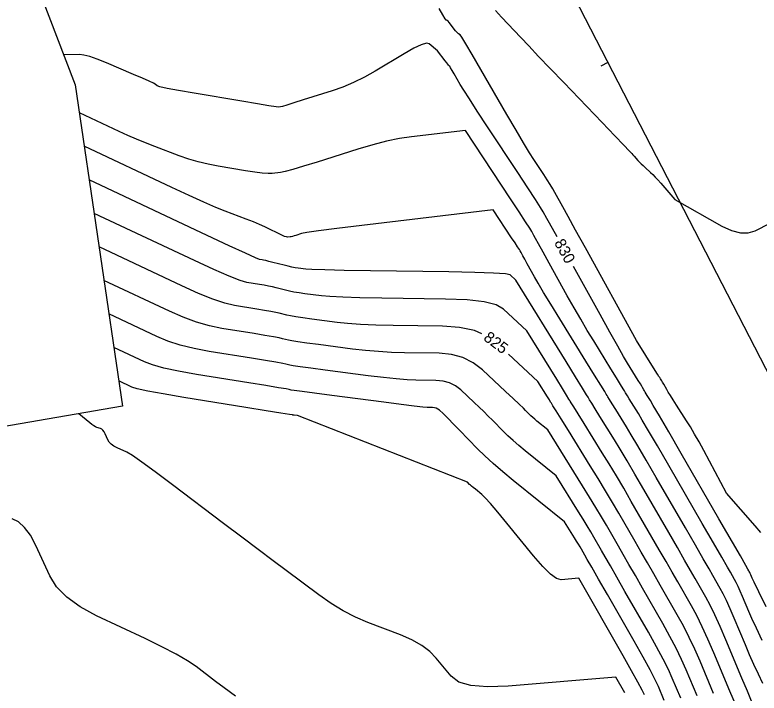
# Model space of a CAD drawing. Extents: x 1715724 to 1716561, y 394063 to 395906.
# Drawn here: x 1716135.4 to 1716227.9, y 394685.4 to 394769.7 of the extents above; entities that cross this region are included whole.
import ezdxf

# ---------------------------------------------------------------- set-up
doc = ezdxf.new("R2010")
doc.units = 0
for name, color, linetype in [('DT_X_Contour_Major', 7, 'Continuous'), ('DT_X_Contour_Minor', 7, 'Continuous'), ('DT_X_TIN_Hull', 7, 'Continuous'), ('GE_P_CL_10', 7, 'Continuous')]:
    doc.layers.add(name, color=color, linetype=linetype)

msp = doc.modelspace()

# ---------------------------------------------------------------- linework, layer by layer
at = {"layer": 'DT_X_Contour_Major'}
for points in [[(1716202.779, 394742.136), (1716201.823, 394743.864), (1716201.508, 394744.435), (1716201.057, 394745.25), (1716200.733, 394745.784), (1716200.099, 394746.776), (1716199.154, 394748.226), (1716197.898, 394750.134), (1716194.137, 394755.831), (1716192.867, 394757.762), (1716191.879, 394759.282), (1716191.172, 394760.391), (1716190.747, 394761.09), (1716189.989, 394762.404), (1716189.738, 394762.837), (1716189.553, 394763.149), (1716189.435, 394763.341), (1716189.384, 394763.412), (1716189.336, 394763.443), (1716189.294, 394763.487), (1716189.205, 394763.594), (1716189.068, 394763.766), (1716188.884, 394764.002), (1716187.916, 394765.253), (1716186.9, 394766.133), (1716186.541, 394766.197), (1716185.9, 394766.012), (1716184.978, 394765.579), (1716183.774, 394764.898), (1716180.187, 394762.749), (1716178.843, 394761.991), (1716177.5, 394761.329), (1716176.158, 394760.762), (1716174.817, 394760.291), (1716171.245, 394759.163), (1716170.063, 394758.791), (1716169.197, 394758.523), (1716168.647, 394758.359), (1716168.413, 394758.298), (1716168.21, 394758.274), (1716167.866, 394758.313), (1716166.986, 394758.446), (1716165.569, 394758.675), (1716163.616, 394758.999), (1716157.693, 394759.99), (1716155.739, 394760.325), (1716154.318, 394760.588), (1716153.432, 394760.779), (1716153.081, 394760.898), (1716152.854, 394761.118), (1716152.623, 394761.256), (1716152.098, 394761.506), (1716151.279, 394761.868), (1716150.168, 394762.342), (1716146.812, 394763.755), (1716145.659, 394764.217), (1716144.715, 394764.545), (1716143.981, 394764.738), (1716143.457, 394764.796), (1716141.5, 394764.752)], [(1716193.44, 394730.1), (1716192.514, 394730.491), (1716190.668, 394730.894), (1716188.522, 394731.05), (1716182.397, 394731.137), (1716180.24, 394731.184), (1716178.361, 394731.262), (1716176.761, 394731.371), (1716175.44, 394731.509), (1716172.289, 394731.92), (1716171.21, 394732.066), (1716170.339, 394732.196), (1716169.674, 394732.311), (1716169.217, 394732.409), (1716168.272, 394732.652), (1716167.832, 394732.753), (1716167.219, 394732.873), (1716166.433, 394733.013), (1716165.474, 394733.173), (1716162.688, 394733.625), (1716161.497, 394733.904), (1716160.016, 394734.4), (1716158.244, 394735.114), (1716156.18, 394736.046), (1716145.873, 394740.903)], [(1716228.745, 394696.184), (1716227.834, 394698.044), (1716227.259, 394699.225), (1716227.022, 394699.728), (1716226.84, 394700.165), (1716226.774, 394700.319), (1716226.714, 394700.451), (1716226.66, 394700.562), (1716226.612, 394700.651), (1716226.492, 394700.862), (1716226.233, 394701.311), (1716225.545, 394702.502), (1716222.885, 394707.108), (1716218.197, 394715.226), (1716216.64, 394717.92), (1716215.485, 394719.912), (1716214.733, 394721.204), (1716214.383, 394721.794), (1716213.986, 394722.434), (1716213.848, 394722.657), (1716213.731, 394722.847), (1716213.637, 394723.004), (1716213.564, 394723.127), (1716213.399, 394723.412), (1716213.298, 394723.581), (1716213.12, 394723.874), (1716212.864, 394724.291), (1716212.53, 394724.831), (1716211.538, 394726.438), (1716211.044, 394727.269), (1716210.308, 394728.556), (1716209.33, 394730.299), (1716208.109, 394732.498), (1716204.812, 394738.46)], [(1716222.214, 394685.387), (1716220.534, 394689.404), (1716219.884, 394690.895), (1716219.193, 394692.356), (1716218.462, 394693.786), (1716217.69, 394695.186), (1716215.579, 394698.88), (1716214.792, 394700.256), (1716214.012, 394701.615), (1716213.24, 394702.957), (1716212.477, 394704.281), (1716210.451, 394707.789), (1716209.659, 394709.145), (1716208.802, 394710.582), (1716207.88, 394712.101), (1716206.894, 394713.701), (1716204.177, 394718.077), (1716203.285, 394719.514), (1716202.646, 394720.543), (1716202.261, 394721.164), (1716202.129, 394721.377), (1716202.115, 394721.402), (1716202.078, 394721.461), (1716201.979, 394721.622), (1716201.818, 394721.883), (1716201.594, 394722.246), (1716200.404, 394724.173), (1716196.759, 394727.579)], [(1716211.199, 394685.469), (1716210.073, 394687.438), (1716196.713, 394686.317), (1716194.122, 394686.213), (1716192.073, 394686.382), (1716190.566, 394686.823), (1716189.602, 394687.537), (1716187.756, 394689.804), (1716186.959, 394690.621), (1716185.955, 394691.371), (1716184.743, 394692.055), (1716183.323, 394692.671), (1716179.261, 394694.226), (1716177.738, 394694.878), (1716176.216, 394695.667), (1716174.696, 394696.593), (1716173.177, 394697.656), (1716169.127, 394700.674), (1716167.501, 394701.889), (1716165.66, 394703.272), (1716163.604, 394704.823), (1716161.333, 394706.541), (1716154.989, 394711.347), (1716152.852, 394712.95), (1716151.197, 394714.155), (1716150.024, 394714.962), (1716149.334, 394715.371), (1716148.138, 394715.932), (1716147.729, 394716.151), (1716147.4, 394716.388), (1716147.151, 394716.643), (1716146.982, 394716.915), (1716146.638, 394717.665), (1716146.505, 394717.917), (1716146.363, 394718.111), (1716146.213, 394718.247), (1716146.054, 394718.324), (1716145.62, 394718.453), (1716145.442, 394718.526), (1716145.232, 394718.647), (1716144.991, 394718.817), (1716144.718, 394719.036), (1716143.373, 394720.171)]]:
    msp.add_lwpolyline(points, dxfattribs=at)
at = {"layer": 'DT_X_Contour_Minor'}
for points in [[(1716228.095, 394705.417), (1716227.375, 394706.241), (1716223.833, 394710.289), (1716221, 394715.579), (1716220.411, 394716.661), (1716219.858, 394717.641), (1716219.341, 394718.518), (1716218.86, 394719.293), (1716217.625, 394721.223), (1716217.202, 394721.887), (1716216.858, 394722.434), (1716216.593, 394722.863), (1716216.408, 394723.174), (1716216.021, 394723.846), (1716215.888, 394724.075), (1716215.781, 394724.257), (1716215.699, 394724.393), (1716215.643, 394724.482), (1716215.527, 394724.657), (1716215.437, 394724.798), (1716215.254, 394725.092), (1716214.977, 394725.538), (1716212.662, 394729.282), (1716206.301, 394740.785), (1716205.079, 394742.994), (1716204.14, 394744.692), (1716203.484, 394745.879), (1716202.492, 394747.672), (1716202.232, 394748.125), (1716201.916, 394748.647), (1716201.544, 394749.237), (1716201.115, 394749.895), (1716199.897, 394751.739), (1716199.345, 394752.608), (1716198.604, 394753.83), (1716197.674, 394755.406), (1716196.553, 394757.336), (1716193.313, 394762.953), (1716192.24, 394764.802), (1716191.452, 394766.137), (1716190.948, 394766.957), (1716190.728, 394767.263), (1716190.522, 394767.394), (1716190.431, 394767.466), (1716190.315, 394767.584), (1716190.172, 394767.749), (1716190.004, 394767.96), (1716189.521, 394768.584), (1716189.358, 394768.789), (1716189.23, 394768.936), (1716189.138, 394769.025), (1716189.082, 394769.056), (1716188.979, 394769.06), (1716188.858, 394769.225), (1716188.572, 394769.717), (1716188.121, 394770.536)], [(1716195.108, 394770.292), (1716195.887, 394769.459), (1716198.259, 394766.932), (1716199.261, 394765.87), (1716200.487, 394764.579), (1716201.938, 394763.059), (1716203.614, 394761.309), (1716208.382, 394756.34), (1716209.947, 394754.709), (1716211.066, 394753.542), (1716211.739, 394752.841), (1716211.967, 394752.604), (1716211.979, 394752.593), (1716212.006, 394752.564), (1716212.076, 394752.486), (1716212.191, 394752.359), (1716212.349, 394752.184), (1716212.828, 394751.65), (1716213.018, 394751.445), (1716213.227, 394751.231), (1716213.456, 394751.009), (1716213.704, 394750.777), (1716214.394, 394750.149), (1716214.667, 394749.888), (1716214.969, 394749.578), (1716215.3, 394749.219), (1716215.661, 394748.811), (1716217.411, 394746.789), (1716223.261, 394743.49), (1716224.459, 394742.923), (1716225.547, 394742.636), (1716226.524, 394742.629), (1716227.391, 394742.901), (1716231.178, 394744.824)], [(1716228.266, 394691.99), (1716227.535, 394693.515), (1716226.978, 394694.713), (1716226.595, 394695.583), (1716225.807, 394697.466), (1716225.525, 394698.126), (1716225.267, 394698.695), (1716225.035, 394699.172), (1716224.828, 394699.558), (1716224.309, 394700.465), (1716223.944, 394701.1), (1716223.238, 394702.325), (1716222.192, 394704.139), (1716220.804, 394706.543), (1716216.648, 394713.738), (1716215.244, 394716.165), (1716214.149, 394718.046), (1716213.363, 394719.383), (1716212.885, 394720.175), (1716212.024, 394721.562), (1716211.735, 394722.028), (1716211.514, 394722.386), (1716211.362, 394722.636), (1716211.277, 394722.777), (1716211.142, 394723.01), (1716210.998, 394723.248), (1716210.668, 394723.786), (1716210.151, 394724.625), (1716209.447, 394725.764), (1716207.323, 394729.204), (1716206.521, 394730.523), (1716205.707, 394731.9), (1716204.882, 394733.335), (1716204.046, 394734.828), (1716201.801, 394738.888), (1716201.051, 394740.244), (1716200.485, 394741.268), (1716200.103, 394741.959), (1716199.905, 394742.317), (1716199.622, 394742.828), (1716199.379, 394743.223), (1716198.861, 394744.027), (1716198.068, 394745.24), (1716197.001, 394746.86), (1716191.379, 394755.376), (1716184.69, 394754.576), (1716183.2, 394754.351), (1716181.594, 394754.019), (1716179.872, 394753.581), (1716178.036, 394753.036), (1716172.985, 394751.441), (1716171.279, 394750.912), (1716169.949, 394750.521), (1716168.995, 394750.267), (1716168.417, 394750.152), (1716167.375, 394750.028), (1716166.875, 394750.014), (1716166.156, 394750.065), (1716165.216, 394750.18), (1716164.058, 394750.36), (1716160.675, 394750.926), (1716159.422, 394751.165), (1716158.2, 394751.46), (1716157.009, 394751.811), (1716155.848, 394752.216), (1716152.794, 394753.371), (1716151.659, 394753.812), (1716150.546, 394754.27), (1716149.453, 394754.745), (1716148.382, 394755.236), (1716143.433, 394757.569)], [(1716228.351, 394686.627), (1716227.788, 394687.795), (1716227.236, 394688.986), (1716226.696, 394690.2), (1716226.168, 394691.437), (1716224.775, 394694.766), (1716224.275, 394695.933), (1716223.82, 394696.939), (1716223.41, 394697.783), (1716223.043, 394698.465), (1716222.127, 394700.069), (1716221.656, 394700.889), (1716220.932, 394702.148), (1716219.954, 394703.843), (1716218.722, 394705.977), (1716215.099, 394712.251), (1716213.848, 394714.41), (1716212.812, 394716.18), (1716211.992, 394717.562), (1716211.387, 394718.557), (1716210.062, 394720.691), (1716209.623, 394721.4), (1716209.297, 394721.925), (1716209.086, 394722.268), (1716208.99, 394722.427), (1716208.885, 394722.608), (1716208.698, 394722.915), (1716208.216, 394723.698), (1716207.438, 394724.959), (1716206.364, 394726.697), (1716203.108, 394731.969), (1716201.997, 394733.776), (1716201.105, 394735.243), (1716200.434, 394736.371), (1716199.982, 394737.159), (1716199.071, 394738.807), (1716198.767, 394739.357), (1716198.537, 394739.772), (1716198.382, 394740.053), (1716198.302, 394740.198), (1716198.187, 394740.405), (1716198.088, 394740.566), (1716197.878, 394740.892), (1716197.556, 394741.384), (1716197.123, 394742.042), (1716194.841, 394745.498), (1716178.523, 394743.546), (1716175.432, 394743.17), (1716173.151, 394742.879), (1716171.68, 394742.672), (1716171.02, 394742.549), (1716170.34, 394742.334), (1716170.103, 394742.262), (1716169.901, 394742.207), (1716169.735, 394742.168), (1716169.605, 394742.146), (1716169.304, 394742.111), (1716169.15, 394742.128), (1716168.911, 394742.206), (1716168.588, 394742.345), (1716168.181, 394742.545), (1716166.983, 394743.16), (1716166.468, 394743.408), (1716165.821, 394743.691), (1716165.043, 394744.008), (1716164.132, 394744.36), (1716161.53, 394745.344), (1716160.385, 394745.804), (1716158.901, 394746.446), (1716157.079, 394747.271), (1716154.918, 394748.278), (1716144.043, 394753.402)], [(1716226.937, 394684.457), (1716226.414, 394685.688), (1716225.741, 394687.291), (1716223.743, 394692.066), (1716223.026, 394693.741), (1716222.373, 394695.183), (1716221.784, 394696.394), (1716221.259, 394697.372), (1716219.944, 394699.673), (1716219.368, 394700.678), (1716218.625, 394701.97), (1716217.716, 394703.548), (1716216.64, 394705.412), (1716213.549, 394710.763), (1716212.451, 394712.655), (1716211.475, 394714.314), (1716210.622, 394715.742), (1716209.89, 394716.938), (1716208.101, 394719.82), (1716207.51, 394720.771), (1716207.08, 394721.464), (1716206.811, 394721.9), (1716206.703, 394722.077), (1716206.628, 394722.206), (1716206.436, 394722.519), (1716205.917, 394723.362), (1716205.069, 394724.736), (1716203.894, 394726.639), (1716197.644, 394736.757), (1716196.946, 394737.409), (1716196.358, 394737.538), (1716194.893, 394737.645), (1716192.551, 394737.729), (1716189.333, 394737.792), (1716179.58, 394737.93), (1716176.337, 394737.98), (1716173.919, 394738.03), (1716172.329, 394738.078), (1716171.565, 394738.124), (1716170.629, 394738.246), (1716170.256, 394738.303), (1716169.838, 394738.383), (1716169.375, 394738.485), (1716168.867, 394738.61), (1716167.453, 394738.972), (1716166.974, 394739.094), (1716166.596, 394739.187), (1716166.321, 394739.25), (1716166.147, 394739.285), (1716165.82, 394739.338), (1716165.32, 394739.54), (1716164.066, 394740.107), (1716162.059, 394741.039), (1716159.298, 394742.335), (1716144.653, 394749.236)], [(1716224.932, 394684.078), (1716224.256, 394685.674), (1716222.258, 394690.45), (1716221.522, 394692.157), (1716220.813, 394693.698), (1716220.13, 394695.072), (1716219.475, 394696.279), (1716217.762, 394699.276), (1716217.08, 394700.467), (1716216.319, 394701.793), (1716215.478, 394703.252), (1716214.558, 394704.846), (1716212, 394709.276), (1716211.055, 394710.9), (1716210.139, 394712.448), (1716209.251, 394713.921), (1716208.392, 394715.32), (1716206.139, 394718.948), (1716205.398, 394720.142), (1716204.863, 394721.004), (1716204.536, 394721.532), (1716204.416, 394721.727), (1716204.371, 394721.804), (1716204.257, 394721.99), (1716203.948, 394722.492), (1716203.443, 394723.309), (1716202.744, 394724.442), (1716199.024, 394730.465), (1716196.124, 394733.175), (1716195.208, 394733.689), (1716193.703, 394734.068), (1716191.61, 394734.312), (1716188.927, 394734.421), (1716180.989, 394734.533), (1716178.288, 394734.582), (1716176.14, 394734.646), (1716174.545, 394734.724), (1716173.502, 394734.817), (1716171.459, 394735.083), (1716170.733, 394735.184), (1716170.088, 394735.289), (1716169.525, 394735.398), (1716169.042, 394735.51), (1716167.863, 394735.812), (1716167.403, 394735.923), (1716166.907, 394736.03), (1716166.377, 394736.132), (1716165.811, 394736.229), (1716164.254, 394736.481), (1716163.409, 394736.722), (1716162.041, 394737.253), (1716160.151, 394738.076), (1716157.739, 394739.19), (1716145.263, 394745.069)], [(1716220.173, 394685.1), (1716218.81, 394688.358), (1716218.245, 394689.632), (1716217.573, 394691.013), (1716216.793, 394692.5), (1716215.906, 394694.093), (1716213.397, 394698.484), (1716212.503, 394700.045), (1716211.705, 394701.438), (1716211.003, 394702.661), (1716210.395, 394703.716), (1716208.902, 394706.301), (1716208.296, 394707.336), (1716207.599, 394708.501), (1716206.81, 394709.797), (1716205.93, 394711.223), (1716201.609, 394718.181), (1716200.272, 394719.258), (1716200, 394719.482), (1716199.754, 394719.695), (1716199.536, 394719.895), (1716199.346, 394720.083), (1716198.874, 394720.567), (1716198.585, 394720.852), (1716198.071, 394721.343), (1716197.333, 394722.039), (1716196.369, 394722.942), (1716193.501, 394725.623), (1716192.358, 394726.505), (1716191.079, 394727.142), (1716189.666, 394727.534), (1716188.117, 394727.679), (1716183.805, 394727.74), (1716182.191, 394727.786), (1716180.582, 394727.878), (1716178.977, 394728.017), (1716177.377, 394728.202), (1716173.118, 394728.757), (1716171.687, 394728.947), (1716170.589, 394729.103), (1716169.824, 394729.224), (1716169.392, 394729.309), (1716168.682, 394729.491), (1716168.261, 394729.582), (1716167.53, 394729.716), (1716166.489, 394729.895), (1716165.138, 394730.117), (1716161.122, 394730.769), (1716159.586, 394731.085), (1716157.991, 394731.546), (1716156.336, 394732.152), (1716154.622, 394732.901), (1716146.483, 394736.736)], [(1716218.131, 394684.814), (1716217.086, 394687.312), (1716216.607, 394688.37), (1716215.953, 394689.671), (1716215.125, 394691.214), (1716214.122, 394693), (1716211.214, 394698.087), (1716210.215, 394699.834), (1716209.399, 394701.261), (1716208.765, 394702.366), (1716208.313, 394703.15), (1716207.353, 394704.814), (1716206.963, 394705.479), (1716206.514, 394706.229), (1716206.007, 394707.062), (1716205.441, 394707.98), (1716202.661, 394712.457), (1716198.798, 394715.567), (1716198.01, 394716.215), (1716197.302, 394716.829), (1716196.672, 394717.407), (1716196.122, 394717.949), (1716194.76, 394719.349), (1716194.235, 394719.881), (1716193.682, 394720.428), (1716193.101, 394720.988), (1716192.492, 394721.564), (1716190.831, 394723.117), (1716190.168, 394723.628), (1716189.428, 394723.997), (1716188.609, 394724.224), (1716187.711, 394724.308), (1716185.213, 394724.344), (1716184.142, 394724.388), (1716182.802, 394724.495), (1716181.193, 394724.663), (1716179.315, 394724.894), (1716173.948, 394725.593), (1716172.165, 394725.829), (1716170.84, 394726.01), (1716169.974, 394726.136), (1716169.566, 394726.209), (1716169.092, 394726.331), (1716168.69, 394726.411), (1716167.841, 394726.559), (1716166.545, 394726.776), (1716164.801, 394727.061), (1716159.556, 394727.913), (1716157.674, 394728.267), (1716155.965, 394728.693), (1716154.428, 394729.189), (1716153.063, 394729.757), (1716147.094, 394732.57)], [(1716216.089, 394684.527), (1716215.362, 394686.266), (1716214.968, 394687.107), (1716214.333, 394688.328), (1716213.456, 394689.928), (1716212.337, 394691.907), (1716209.032, 394697.691), (1716207.927, 394699.623), (1716207.092, 394701.083), (1716206.527, 394702.07), (1716206.232, 394702.585), (1716205.803, 394703.326), (1716205.63, 394703.623), (1716205.43, 394703.957), (1716205.204, 394704.328), (1716204.951, 394704.737), (1716203.712, 394706.733), (1716197.324, 394711.876), (1716196.021, 394712.948), (1716194.849, 394713.963), (1716193.808, 394714.918), (1716192.898, 394715.816), (1716190.645, 394718.131), (1716189.885, 394718.91), (1716189.293, 394719.513), (1716188.87, 394719.938), (1716188.615, 394720.186), (1716188.16, 394720.611), (1716187.979, 394720.751), (1716187.776, 394720.852), (1716187.551, 394720.914), (1716187.306, 394720.938), (1716186.622, 394720.947), (1716186.094, 394720.99), (1716185.023, 394721.111), (1716183.409, 394721.31), (1716181.253, 394721.587), (1716174.778, 394722.43), (1716172.642, 394722.71), (1716171.091, 394722.916), (1716170.124, 394723.049), (1716169.741, 394723.109), (1716169.501, 394723.171), (1716169.119, 394723.24), (1716168.152, 394723.403), (1716166.601, 394723.658), (1716164.465, 394724.005), (1716157.99, 394725.056), (1716155.763, 394725.449), (1716153.94, 394725.839), (1716152.521, 394726.227), (1716151.504, 394726.612), (1716147.704, 394728.403)], [(1716213.638, 394685.22), (1716213.356, 394685.799), (1716212.817, 394686.803), (1716212.022, 394688.232), (1716210.97, 394690.085), (1716205.461, 394699.723), (1716203.273, 394699.54), (1716202.707, 394699.696), (1716201.948, 394700.244), (1716200.995, 394701.183), (1716199.849, 394702.513), (1716196.534, 394706.583), (1716195.409, 394707.949), (1716194.519, 394708.994), (1716193.863, 394709.719), (1716193.443, 394710.123), (1716192.636, 394710.772), (1716192.364, 394710.993), (1716192.153, 394711.168), (1716192.003, 394711.296), (1716191.915, 394711.379), (1716191.645, 394711.656), (1716170.544, 394719.927), (1716170.107, 394719.984), (1716170.025, 394719.994), (1716169.966, 394720.002), (1716169.93, 394720.007), (1716169.916, 394720.009), (1716169.911, 394720.01), (1716169.548, 394720.07), (1716168.463, 394720.246), (1716166.656, 394720.539), (1716164.128, 394720.949), (1716156.424, 394722.2), (1716153.852, 394722.631), (1716151.915, 394722.986), (1716150.613, 394723.265), (1716149.946, 394723.468), (1716148.314, 394724.236)], [(1716162.817, 394685.053), (1716161.424, 394686.098), (1716160.355, 394686.904), (1716157.937, 394688.736), (1716156.861, 394689.47), (1716155.447, 394690.296), (1716153.693, 394691.216), (1716151.601, 394692.229), (1716145.571, 394695.053), (1716143.512, 394696.157), (1716141.855, 394697.351), (1716140.6, 394698.634), (1716139.749, 394700.006), (1716138.015, 394703.786), (1716137.344, 394705.056), (1716136.63, 394706.034), (1716135.874, 394706.717), (1716135.075, 394707.107)]]:
    msp.add_lwpolyline(points, dxfattribs=at)
at = {"layer": 'DT_X_TIN_Hull'}
msp.add_lwpolyline([(1716124.186, 394809.786), (1716142.923, 394761.049), (1716148.773, 394721.102), (1716073.406, 394708.116)], dxfattribs=at)
at = {"layer": 'GE_P_CL_10'}
for p, q in [((1716249.46, 394685.42), (1715852.538, 395456.564)), ((1716209.1, 394763.833), (1716208.211, 394763.375))]:
    msp.add_line(p, q, dxfattribs=at)

# ---------------------------------------------------------------- texts
at = {"layer": 'DT_X_Contour_Major'}
for s, rotation, p in [('830', 298.94217, (1716202.377, 394741.416)), ('825', 322.78216, (1716193.534, 394729.402))]:
    msp.add_text(s, height=1.4, rotation=rotation, dxfattribs=at).set_placement(p)

doc.saveas('drawing.dxf')
